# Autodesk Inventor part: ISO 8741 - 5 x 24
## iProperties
Created: 2008-08
Part Number: ISO 8741 - 5 x 24
Material: BgAAAEgAAABOAEEATQBFAFMACgBNAGEAdABlAHIAaQBhAGwAcwAKADEAOgBTAHQAZQBlAGwALAAgAE0AaQBsAGQACgAKAEUATgBEAAoAAAA=
Description: Kerbstift
Vendor: Autodesk Inc.
Document SubType Name: Modeling
Standard: ISO 8741
Designer: U.Rapp
Standards Organization: DIN
Language: de-DE
Size Designation: 5 x 24
Categories: <MemberInstance Version="R10.0.0"><Categories><Category DisplayName="Schrauben" InternalName="e4da775c-781d-43d5-af7c-5136215cf5a6" Mnemonic="FSTN"><Category Di
Author: U.Rapp
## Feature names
1. Körper [Revolution]
2. Nut [Extrusion]
3. Nuten [Circular Pattern]
